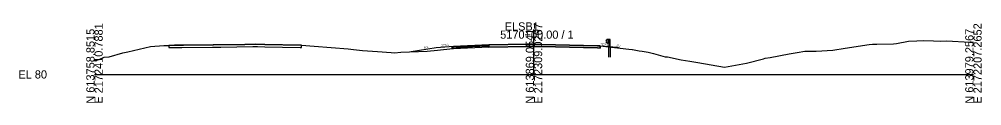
# Model space of a CAD drawing. Extents: x -26 to 1303, y -3010 to 12023.
# Drawn here: x -25.7 to 302.8, y -1009.7 to -982.2 of the extents above; entities that cross this region are included whole.
import ezdxf

# ---------------------------------------------------------------- set-up
doc = ezdxf.new("R2010")
doc.units = 0
for name, color, linetype in [('RD_GPK_XS_Cell', 7, 'Continuous'), ('RD_PD_Final_TrvlWay', 7, 'Continuous'), ('RD_XS_Base', 7, 'Continuous'), ('RD_XS_ExGround', 7, 'Continuous'), ('RD_XS_ExPaveRet', 7, 'Continuous'), ('RD_XS_GR', 7, 'Continuous'), ('RD_XS_Greenside', 7, 'Continuous'), ('RD_XS_Pave', 7, 'Continuous'), ('RD_XS_PaveOvlay_CP', 7, 'Continuous'), ('RD_XS_TieSlope', 7, 'Continuous'), ('RD_XS_TX_ShdSlope', 7, 'Continuous'), ('RD_XS_TX_Slope', 7, 'Continuous')]:
    doc.layers.add(name, color=color, linetype=linetype)

msp = doc.modelspace()

# ---------------------------------------------------------------- linework, layer by layer
at = {"layer": 'RD_GPK_XS_Cell'}
for p, q in [((150, -1000), (150, -985)), ((0, -1000), (150, -1000)), ((150, -1000), (300, -1000))]:
    msp.add_line(p, q, dxfattribs=at)
at = {"layer": 'RD_PD_Final_TrvlWay'}
for p, q in [((175.53, -994.08), (175.53, -990.48)), ((175.53, -990.48), (176.03, -990.52)), ((176.03, -990.52), (176.03, -994.08))]:
    msp.add_line(p, q, dxfattribs=at)
at = {"layer": 'RD_XS_Base'}
for p, q in [((122.06, -990.74), (122.56, -990.72)), ((122.06, -991.24), (122.06, -990.74)), ((122.06, -990.74), (122.06, -990.74)), ((122.56, -991.22), (122.06, -991.24)), ((122.06, -991.24), (122.06, -991.24)), ((122.06, -991.24), (122.06, -991.24)), ((122.56, -990.72), (134.55, -990.24)), ((122.56, -990.72), (122.56, -990.72)), ((134.55, -990.74), (122.56, -991.22)), ((122.56, -991.22), (122.56, -991.22)), ((134.55, -990.68), (134.55, -990.74))]:
    msp.add_line(p, q, dxfattribs=at)
at = {"layer": 'RD_XS_ExGround'}
msp.add_lwpolyline([(0, -995.35), (1.58, -994.91), (3.32, -994.14), (4.96, -994), (9.68, -992.66), (11.36, -992.26), (19.11, -990.44), (23.64, -990.14), (25.41, -990.07), (30.32, -990.02), (40.64, -989.94), (51.34, -989.77), (54.98, -989.71), (58.09, -989.78), (70.68, -990.01), (74.93, -990.29), (86.54, -991.31), (88.44, -991.5), (91.44, -991.85), (96.59, -992.14), (101.3, -992.49), (102.4, -992.57), (104.5, -992.45), (113.55, -992.09), (117.04, -991.68), (122.35, -991.18), (134.55, -989.93), (147.65, -989.7), (147.67, -989.7), (150.06, -989.66), (152.59, -989.72), (172.59, -990.24), (182.39, -991.37), (183.49, -991.5), (183.63, -991.51), (185.9, -991.91), (186.9, -992.08), (188.96, -992.44), (190.82, -992.88), (194.79, -993.98), (195.53, -994.03), (200.24, -995.04), (203.17, -995.5), (205.95, -995.9), (215, -997.47), (222.51, -996.11), (228.37, -994.67), (228.89, -994.46), (230.64, -994.19), (237.11, -993.01), (239.89, -992.5), (242.43, -992.02), (245.99, -992.02), (246.28, -992.11), (252.01, -991.75), (256.2, -991.04), (264.38, -989.81), (265.51, -989.64), (265.69, -989.62), (267.01, -989.61), (272.67, -989.55), (273.76, -989.41), (277.82, -988.63), (280.7, -988.57), (282.88, -988.44), (286.41, -988.49), (288.9, -988.67), (290.8, -988.57), (298.85, -988.97), (300, -988.96)], dxfattribs=at)
at = {"layer": 'RD_XS_ExPaveRet'}
for points in [[(58.09, -989.78), (55.66, -989.73), (54.98, -989.71), (54.79, -989.72), (54, -989.73), (43.13, -989.9), (40.64, -989.94), (40.55, -989.94), (40.31, -989.95), (29.83, -990.03), (27.28, -990.05), (25.41, -990.07), (25.41, -990.68), (25.41, -990.82), (27.28, -990.8), (29.83, -990.78), (40.31, -990.7), (40.55, -990.69), (40.64, -990.69), (43.13, -990.65), (54, -990.48), (54.79, -990.47), (54.98, -990.46), (55.66, -990.48), (58.09, -990.53), (70.22, -990.75), (70.68, -990.76), (70.68, -990.62), (70.68, -990.01), (70.22, -990), (58.09, -989.78)], [(25.41, -990.07), (25.41, -990.68), (25.41, -990.82), (27.28, -990.8), (29.83, -990.78), (40.31, -990.7), (40.55, -990.69), (40.64, -990.69), (43.13, -990.65), (54, -990.48), (54.79, -990.47), (54.98, -990.46), (55.66, -990.48), (58.09, -990.53), (70.22, -990.75), (70.68, -990.76), (70.68, -990.62), (70.68, -990.01), (70.22, -990), (58.09, -989.78), (55.66, -989.73), (54.98, -989.71)], [(29.84, -990.03), (29.83, -990.03), (27.28, -990.05), (25.41, -990.07)], [(40.64, -989.94), (40.55, -989.94), (40.31, -989.95), (29.84, -990.03)], [(54, -989.73), (51.34, -989.77), (40.64, -989.94)], [(54.98, -989.71), (54.79, -989.72), (54, -989.73)], [(172.59, -990.24), (172.59, -990.24), (172.59, -990.88), (172.59, -990.99), (172.59, -990.99), (172.59, -990.99), (171.63, -990.97), (152.59, -990.47), (150.13, -990.41), (150.06, -990.41), (150, -990.41), (150, -990.41), (147.67, -990.45), (134.56, -990.68), (134.55, -990.68), (134.55, -990.68), (134.55, -990.68), (134.55, -990.68), (134.55, -990.56), (134.55, -989.93), (134.55, -989.93), (134.55, -989.93), (134.55, -989.93), (134.56, -989.93), (147.67, -989.7), (150, -989.66), (150, -989.66), (150.06, -989.66), (150.13, -989.66), (152.59, -989.72), (171.63, -990.22), (172.59, -990.24), (172.59, -990.24)], [(150, -989.66), (150, -989.66), (147.67, -989.7), (147.67, -989.7), (147.65, -989.7), (134.56, -989.93), (134.55, -989.93)], [(134.55, -989.93), (134.55, -989.93), (134.55, -990.56), (134.55, -990.68), (134.55, -990.68), (134.56, -990.68), (147.67, -990.45), (150, -990.41), (150, -990.41), (150.06, -990.41), (150.13, -990.41), (152.59, -990.47), (171.63, -990.97), (172.59, -990.99), (172.59, -990.88), (172.59, -990.24)], [(152.59, -989.72), (150.13, -989.66), (150.06, -989.66), (150, -989.66)], [(172.59, -990.24), (171.63, -990.22), (152.59, -989.72)]]:
    msp.add_lwpolyline(points, dxfattribs=at)
at = {"layer": 'RD_XS_GR'}
for p, q in [((174.59, -988.37), (174.79, -988.16)), ((174.66, -988.45), (174.59, -988.37)), ((174.59, -988.96), (174.79, -988.74)), ((174.86, -988.67), (174.66, -988.45)), ((174.79, -988.16), (174.86, -988.08)), ((174.79, -988.74), (174.86, -988.67)), ((174.86, -988.08), (174.86, -989.25)), ((175.53, -988.08), (174.86, -988.08)), ((174.86, -988.08), (174.86, -988.39)), ((174.86, -988.39), (174.86, -989.25)), ((175.53, -988.08), (175.53, -990.48)), ((175.78, -988.08), (175.53, -988.08)), ((175.53, -989.25), (175.53, -988.08)), ((176.03, -988.08), (175.78, -988.08)), ((176.03, -990.52), (176.03, -988.08)), ((174.66, -989.03), (174.59, -988.96)), ((174.86, -989.25), (174.66, -989.03)), ((174.86, -989.25), (175.53, -989.25)), ((175.53, -990.48), (176.03, -990.52))]:
    msp.add_line(p, q, dxfattribs=at)
at = {"layer": 'RD_XS_Greenside'}
for p, q in [((116.56, -990.89), (108.05, -992.3)), ((178.34, -990.7), (178.86, -990.96))]:
    msp.add_line(p, q, dxfattribs=at)
at = {"layer": 'RD_XS_Pave'}
for p, q in [((134.55, -989.93), (122.56, -990.41)), ((134.55, -990.09), (122.56, -990.56)), ((122.56, -990.56), (134.55, -990.09)), ((122.56, -990.72), (134.55, -990.24)), ((122.56, -990.41), (122.56, -990.41)), ((122.56, -990.41), (122.56, -990.56)), ((122.56, -990.56), (122.56, -990.56)), ((122.56, -990.56), (122.56, -990.72)), ((122.56, -990.56), (122.56, -990.56)), ((122.56, -990.56), (122.56, -990.56)), ((122.56, -990.72), (122.56, -990.72)), ((122.56, -990.72), (122.56, -990.72))]:
    msp.add_line(p, q, dxfattribs=at)
at = {"layer": 'RD_XS_PaveOvlay_CP'}
for p in [(134.55, -989.93), (122.56, -990.41)]:
    msp.add_line(p, (122.56, -990.41), dxfattribs=at)
at = {"layer": 'RD_XS_TieSlope'}
for p, q in [((122.56, -990.41), (116.56, -990.89)), ((172.59, -990.24), (178.34, -990.7))]:
    msp.add_line(p, q, dxfattribs=at)

# ---------------------------------------------------------------- texts
at = {"layer": 'RD_GPK_XS_Cell'}
for s, p in [('ELSB1', (140, -985)), ('5170+00.00 / 1', (138.46, -987.8)), ('EL 80', (-26, -1001.4))]:
    msp.add_text(s, height=2.8, dxfattribs=at).set_placement(p)
for s, p in [('N 613758.8515', (0, -1010)), ('E 2172410.7881', (2.8, -1010)), ('N 613869.0541', (150, -1010)), ('E 2172309.0267', (152.8, -1010)), ('N 613979.2567', (300, -1010)), ('E 2172207.2652', (302.8, -1010))]:
    msp.add_text(s, height=2.8, rotation=90, dxfattribs=at).set_placement(p)
at = {"layer": 'RD_XS_TX_ShdSlope'}
for rotation, p in [(4.5739, (118.1, -990.46)), (355.4261, (172.56, -989.96))]:
    msp.add_text('12.5:1', height=0.75, rotation=rotation, dxfattribs=at).set_placement(p)
at = {"layer": 'RD_XS_TX_Slope'}
for s, rotation, p in [('6:1', 9.4642, (112.53, -991.19)), ('2:1', 333.4349, (178.08, -990.28))]:
    msp.add_text(s, height=0.75, rotation=rotation, dxfattribs=at).set_placement(p)

doc.saveas('drawing.dxf')
